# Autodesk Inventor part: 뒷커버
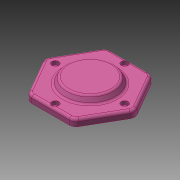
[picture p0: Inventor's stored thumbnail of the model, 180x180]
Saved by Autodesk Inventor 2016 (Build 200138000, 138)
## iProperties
Created: 2013-02
Part Number: 뒷커버
Document SubType Name: Modeling
Density: 1 g/cm^3
Material: 일반
Appearance: 분홍색
Author: 한국산업디자인학원[gmhk.co.kr]
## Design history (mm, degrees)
sketch "스케치1" dims "d37" = 105
  geometry: L1 (50.191, -4)-(28.559, -41.466); L2 (21.631, -45.466)-(-21.631, -45.466); L3 (-28.559, -41.466)-(-50.191, -4); L4 (-50.191, 4)-(-28.559, 41.466); L5 (-21.631, 45.466)-(21.631, 45.466); L6 (28.559, 41.466)-(50.191, 4); C1 r 30 at (0, 0); A1 r 8 centre (-21.631, 37.466) between (-21.631, 45.466) and (-28.559, 41.466); A2 r 8 centre (21.631, 37.466) between (28.559, 41.466) and (21.631, 45.466); A3 r 8 centre (43.262, 0) between (50.191, -4) and (50.191, 4); A4 r 8 centre (21.631, -37.466) between (21.631, -45.466) and (28.559, -41.466); A5 r 8 centre (-21.631, -37.466) between (-28.559, -41.466) and (-21.631, -45.466); A6 r 8 centre (-43.262, 0) between (-50.191, 4) and (-50.191, -4); 9 further points
  constraints: 12 end point, 12 point on circle, 12 point on line, 12 tangent, 7 centre point, 5 equal radius, 3 coincident, 1 horizontal, 1 horizontal alignment, 15 other
  dimensions: "d39" = 60 diameter of C1; "d40" = 8 radius of A1
extrude "돌출1" new body sketch "스케치1" distance "d0" = 8; taper "d1" = 0 deg
sketch "스케치2"
  geometry: C1 r 30 at (0, 0); 1 further point
  constraints: 1 centre point, 1 coincident
  dimensions: "d2" = 60 diameter of C1
extrude "돌출2" join sketch "스케치2" distance "d3" = 7; taper "d4" = -30 deg
sketch "스케치3"
  geometry: C1 r 30 at (0, 0) reference; A1 r 40 centre (0, 0) between (0, 40) and (-40, 0); 2 further points
  constraints: 4 point on circle, 2 horizontal alignment, 2 vertical alignment, 1 centre point, 1 coincident
  dimensions: "d47" = 80 diameter of A1
hole "구멍2" sketch "스케치3" at (0, 40), (-40, 0), (0, -40), (40, 0) diameter "d14" = 4.5; stored, may be unused: countersink angle "d18" = 90 deg, drill point angle "d20" = 118 deg; dims "d15" = 6, "d16" = 8, "d17" = 4.4, "d19" = 20
extrude "돌출3" join sketch "스케치1" distance "d21" = 12; taper "d22" = 0 deg
hole "구멍3" diameter "d25" = 30; stored, may be unused: countersink angle "d29" = 90 deg, drill point angle "d31" = 0 deg; dims "d26" = 6, "d27" = 42, "d28" = 13, "d30" = 16, "d50" = 10, "d51" = 10
fillet "모깎기1" dims "d32" = 3, "d33" = 1
chamfer "모따기1" distance "d34" = 1; stored, may be unused: second distance "d35" = 2, angle "d36" = 45 deg
chamfer "모따기2" distance "d43" = 1; stored, may be unused: second distance "d44" = 2, angle "d45" = 45 deg
fillet "모깎기2" dims "d46" = 3
node "솔리드1"
